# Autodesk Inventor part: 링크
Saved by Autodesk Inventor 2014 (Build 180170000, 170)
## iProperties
Created: 2024-08
Part Number: 링크
Material: 일반
Document SubType Name: Modeling
Designer: dg
Density: 1 g/cm^3
Appearance: 기본값
Author: dg
Author: jhkim
Creation Date: 2024-08-09
Sending System: Autodesk Inventor 2025
Preprocessor: ST-DEVELOPER v20
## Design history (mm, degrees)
node "링크1"
node "솔리드1"
node "기준1"
